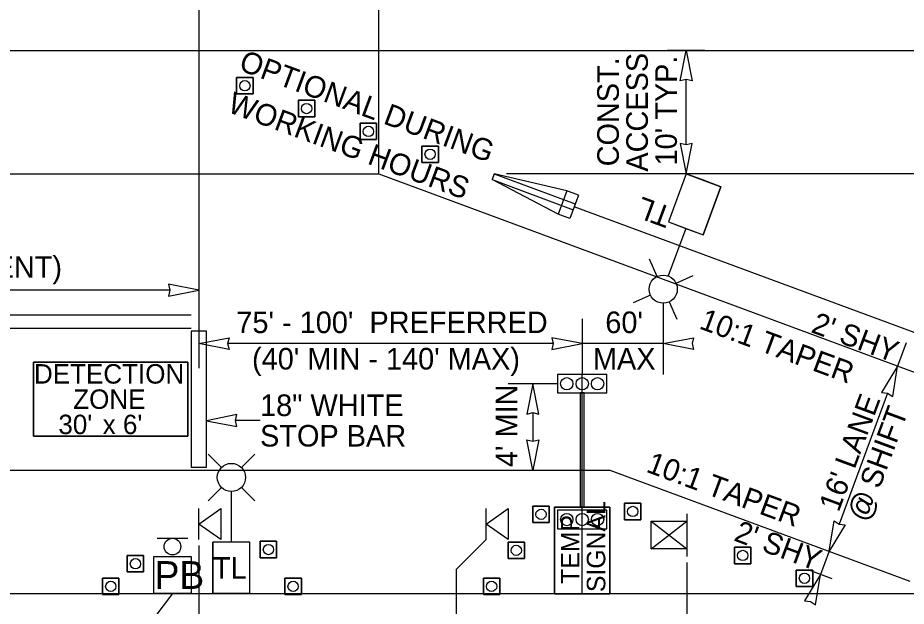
# Model space of a CAD drawing. Extents: x 99976 to 100136, y 99905 to 100011.
# Drawn here: x 100009.271 to 100012.15, y 99946.138 to 99948.045 of the extents above; entities that cross this region are included whole.
import ezdxf

# ---------------------------------------------------------------- set-up
doc = ezdxf.new("R2010")
doc.units = 0
for name, color, linetype in [('RD_ED_ShoulderPavedEdge', 7, 'Continuous'), ('RD_MK_LineEdgeWhite', 7, 'Continuous'), ('RD_MK_LineNoPass', 7, 'Continuous'), ('TR_WZ_BarrierTemp', 7, 'Continuous'), ('TR_WZ_PortableLightStandard', 7, 'Continuous'), ('TR_WZ_PortableSignMount5ftMinBlk-Wht', 7, 'Continuous'), ('TR_WZ_PortableSignMountBlk-Wht', 7, 'Continuous'), ('TR_WZ_ScaleTerminalEndSection', 7, 'Continuous'), ('TR_WZ_Sign', 7, 'Continuous'), ('TR_WZ_TempSignal', 7, 'Continuous'), ('TR_WZ_TrafficCone', 7, 'Continuous'), ('TR_WZ_WorkZoneDetails', 7, 'Continuous'), ('TR_WZ_WorkZoneTextCurrent', 7, 'Continuous')]:
    doc.layers.add(name, color=color, linetype=linetype)

msp = doc.modelspace()

# ---------------------------------------------------------------- linework, layer by layer
at = {"layer": 'RD_ED_ShoulderPavedEdge'}
for p, q in [((100000.1076, 99947.9393), (100015.45, 99947.9393)), ((100000.1076, 99946.1793), (100015.45, 99946.1793))]:
    msp.add_line(p, q, dxfattribs=at)
at = {"layer": 'RD_MK_LineEdgeWhite'}
for p, q in [((100000.1076, 99947.5393), (100010.4406, 99947.5393)), ((100010.4406, 99947.5393), (100012.9246, 99946.6193)), ((100000.1076, 99946.5793), (100011.1899, 99946.5793)), ((100011.1899, 99946.5793), (100012.1619, 99946.2193))]:
    msp.add_line(p, q, dxfattribs=at)
at = {"layer": 'RD_MK_LineNoPass'}
for p, q in [((100006.4076, 99947.0826), (100009.8326, 99947.0826)), ((100006.4076, 99947.0393), (100009.8326, 99947.0393))]:
    msp.add_line(p, q, dxfattribs=at)
at = {"layer": 'TR_WZ_BarrierTemp'}
msp.add_line((100012.9895, 99946.7232), (100011.074, 99947.4327), dxfattribs=at)
at = {"layer": 'TR_WZ_PortableLightStandard'}
for p, q in [((100011.4367, 99947.5393), (100011.3791, 99947.3837)), ((100011.4367, 99947.5393), (100011.3791, 99947.3837)), ((100011.4367, 99947.5393), (100011.5492, 99947.4976)), ((100011.5492, 99947.4976), (100011.4916, 99947.342)), ((100011.4916, 99947.342), (100011.5492, 99947.4976)), ((100011.3791, 99947.3837), (100011.4916, 99947.342)), ((100011.4353, 99947.3628), (100011.3782, 99947.2087)), ((100011.3432, 99947.2073), (100011.3178, 99947.2626)), ((100011.4039, 99947.1848), (100011.4593, 99947.2103)), ((100011.3207, 99947.1467), (100011.2655, 99947.1212)), ((100011.3815, 99947.1242), (100011.4069, 99947.0688)), ((100009.9312, 99946.5878), (100009.8881, 99946.6309)), ((100009.996, 99946.5878), (100010.0389, 99946.6309)), ((100009.9312, 99946.5231), (100009.8881, 99946.48)), ((100009.996, 99946.5231), (100010.0389, 99946.48)), ((100009.9636, 99946.3453), (100009.9636, 99946.5097)), ((100009.9036, 99946.1793), (100009.9036, 99946.3453)), ((100010.0236, 99946.3453), (100009.9036, 99946.3453)), ((100009.9036, 99946.3453), (100009.9036, 99946.1793)), ((100010.0236, 99946.1793), (100010.0236, 99946.3453)), ((100010.0236, 99946.1793), (100010.0236, 99946.3453)), ((100010.0236, 99946.1793), (100009.9036, 99946.1793))]:
    msp.add_line(p, q, dxfattribs=at)
for points in [[(100011.5492, 99947.4976), (100011.493, 99947.5185), (100011.4367, 99947.5393)], [(100011.3791, 99947.3837), (100011.4353, 99947.3628), (100011.4916, 99947.342)], [(100010.0236, 99946.3453), (100009.9636, 99946.3453), (100009.9036, 99946.3453)], [(100009.9036, 99946.1793), (100009.9636, 99946.1793), (100010.0236, 99946.1793)]]:
    msp.add_lwpolyline(points, dxfattribs=at)
for centre in [(100011.3623, 99947.1657), (100011.3623, 99947.1657), (100009.9635, 99946.5555), (100009.9635, 99946.5555)]:
    msp.add_circle(centre, 0.0457, dxfattribs=at)
at = {"layer": 'TR_WZ_PortableSignMount5ftMinBlk-Wht'}
for p, q in [((100011.4384, 99946.4376), (100011.4384, 99946.2997)), ((100011.3233, 99946.3238), (100011.4384, 99946.4134)), ((100011.3233, 99946.4134), (100011.4384, 99946.3238)), ((100011.3807, 99946.3685), (100011.3807, 99946.3685)), ((100011.3808, 99946.3686), (100011.3808, 99946.3686))]:
    msp.add_line(p, q, dxfattribs=at)
msp.add_lwpolyline([(100011.3233, 99946.3238), (100011.3233, 99946.4134), (100011.4384, 99946.4134), (100011.4384, 99946.3238)], close=True, dxfattribs=at)
at = {"layer": 'TR_WZ_PortableSignMountBlk-Wht'}
for p, q in [((100009.8576, 99946.3547), (100009.8576, 99946.4547)), ((100010.7884, 99946.3547), (100010.7884, 99946.4547))]:
    msp.add_line(p, q, dxfattribs=at)
for points in [[(100009.8576, 99946.4046), (100009.9294, 99946.4547), (100009.9294, 99946.3547)], [(100010.7884, 99946.4046), (100010.8602, 99946.4547), (100010.8602, 99946.3547)]]:
    msp.add_lwpolyline(points, close=True, dxfattribs=at)
at = {"layer": 'TR_WZ_ScaleTerminalEndSection'}
for p, q in [((100010.8149, 99947.5393), (100010.8079, 99947.5206)), ((100010.8149, 99947.5393), (100011.0775, 99947.4421)), ((100011.0504, 99947.4841), (100010.8149, 99947.5393)), ((100010.8079, 99947.5206), (100011.0705, 99947.4233)), ((100011.0226, 99947.4091), (100010.8079, 99947.5206)), ((100011.0504, 99947.4841), (100011.0226, 99947.4091)), ((100011.0879, 99947.4702), (100011.0504, 99947.4841)), ((100011.0879, 99947.4702), (100011.0601, 99947.3952)), ((100011.0601, 99947.3952), (100011.0226, 99947.4091))]:
    msp.add_line(p, q, dxfattribs=at)
at = {"layer": 'TR_WZ_Sign'}
msp.add_line((100009.7226, 99946.3583), (100009.8226, 99946.3583), dxfattribs=at)
msp.add_circle((100009.7726, 99946.3313), 0.027, dxfattribs=at)
msp.add_circle((100009.7726, 99946.3313), 0.027, dxfattribs=at)
at = {"layer": 'TR_WZ_TempSignal'}
for p, q in [((100011.02, 99946.8893), (100011.02, 99946.8293)), ((100011.1798, 99946.8893), (100011.02, 99946.8893)), ((100011.0999, 99946.1789), (100011.0999, 99946.8893)), ((100011.1798, 99946.8293), (100011.1798, 99946.8893)), ((100011.02, 99946.8293), (100011.1798, 99946.8293)), ((100011.0932, 99946.8293), (100011.0932, 99946.4591)), ((100011.1065, 99946.8293), (100011.0932, 99946.8293)), ((100011.1065, 99946.4591), (100011.1065, 99946.8293)), ((100011.0098, 99946.1789), (100011.0098, 99946.4591)), ((100011.0098, 99946.4591), (100011.1899, 99946.4591)), ((100011.0932, 99946.4591), (100011.0098, 99946.4591)), ((100011.0098, 99946.4591), (100011.0098, 99946.1789)), ((100011.0932, 99946.4591), (100011.1065, 99946.4591)), ((100011.1065, 99946.4591), (100011.0932, 99946.4591)), ((100011.1899, 99946.4591), (100011.1065, 99946.4591)), ((100011.1899, 99946.4591), (100011.1899, 99946.1789)), ((100011.1899, 99946.1789), (100011.1899, 99946.4591)), ((100011.02, 99946.4491), (100011.02, 99946.3891)), ((100011.1798, 99946.4491), (100011.02, 99946.4491)), ((100011.1798, 99946.3891), (100011.1798, 99946.4491)), ((100011.02, 99946.3891), (100011.1798, 99946.3891)), ((100011.1899, 99946.1789), (100011.0098, 99946.1789)), ((100011.0098, 99946.1789), (100011.1899, 99946.1789))]:
    msp.add_line(p, q, dxfattribs=at)
for points in [[(100011.1798, 99946.8293), (100011.1798, 99946.8893), (100011.02, 99946.8893), (100011.02, 99946.8293), (100011.1798, 99946.8293)], [(100011.1798, 99946.3891), (100011.1798, 99946.4491), (100011.02, 99946.4491), (100011.02, 99946.3891), (100011.1798, 99946.3891)]]:
    msp.add_lwpolyline(points, dxfattribs=at)
msp.add_lwpolyline([(100009.7126, 99946.2993), (100009.8326, 99946.2993), (100009.8326, 99946.1793), (100009.7126, 99946.1793)], close=True, dxfattribs=at)
msp.add_lwpolyline([(100009.7126, 99946.2993), (100009.8326, 99946.2993), (100009.8326, 99946.1793), (100009.7126, 99946.1793)], close=True, dxfattribs=at)
for centre in [(100011.0499, 99946.8593), (100011.0499, 99946.8593), (100011.0999, 99946.8593), (100011.0999, 99946.8593), (100011.1498, 99946.8593), (100011.1498, 99946.8593), (100011.0499, 99946.4191), (100011.0499, 99946.4191), (100011.0999, 99946.4191), (100011.0999, 99946.4191), (100011.1498, 99946.4191), (100011.1498, 99946.4191)]:
    msp.add_circle(centre, 0.02, dxfattribs=at)
at = {"layer": 'TR_WZ_TrafficCone'}
for points in [[(100010.0339, 99947.8518), (100009.9805, 99947.8518), (100009.9805, 99947.7984), (100010.0339, 99947.7984), (100010.0339, 99947.8518)], [(100010.0339, 99947.7984), (100009.9805, 99947.7984), (100009.9805, 99947.8518), (100010.0339, 99947.8518), (100010.0339, 99947.7984)], [(100010.2339, 99947.7777), (100010.1805, 99947.7777), (100010.1805, 99947.7244), (100010.2339, 99947.7244), (100010.2339, 99947.7777)], [(100010.2339, 99947.7244), (100010.1805, 99947.7244), (100010.1805, 99947.7777), (100010.2339, 99947.7777), (100010.2339, 99947.7244)], [(100010.4339, 99947.7036), (100010.3805, 99947.7036), (100010.3805, 99947.6503), (100010.4339, 99947.6503), (100010.4339, 99947.7036)], [(100010.4339, 99947.6503), (100010.3805, 99947.6503), (100010.3805, 99947.7036), (100010.4339, 99947.7036), (100010.4339, 99947.6503)], [(100010.6339, 99947.6295), (100010.5805, 99947.6295), (100010.5805, 99947.5762), (100010.6339, 99947.5762), (100010.6339, 99947.6295)], [(100010.6339, 99947.5762), (100010.5805, 99947.5762), (100010.5805, 99947.6295), (100010.6339, 99947.6295), (100010.6339, 99947.5762)], [(100010.9931, 99946.4626), (100010.9398, 99946.4626), (100010.9398, 99946.4093), (100010.9931, 99946.4093), (100010.9931, 99946.4626)], [(100010.9931, 99946.4093), (100010.9398, 99946.4093), (100010.9398, 99946.4626), (100010.9931, 99946.4626), (100010.9931, 99946.4093)], [(100011.237, 99946.472), (100011.2903, 99946.472), (100011.2903, 99946.4187), (100011.237, 99946.4187), (100011.237, 99946.472)], [(100011.237, 99946.4187), (100011.2903, 99946.4187), (100011.2903, 99946.472), (100011.237, 99946.472), (100011.237, 99946.4187)], [(100010.1101, 99946.3486), (100010.0568, 99946.3486), (100010.0568, 99946.2953), (100010.1101, 99946.2953), (100010.1101, 99946.3486)], [(100010.1101, 99946.2953), (100010.0568, 99946.2953), (100010.0568, 99946.3486), (100010.1101, 99946.3486), (100010.1101, 99946.2953)], [(100010.8599, 99946.346), (100010.9132, 99946.346), (100010.9132, 99946.2926), (100010.8599, 99946.2926), (100010.8599, 99946.346)], [(100010.8599, 99946.2926), (100010.9132, 99946.2926), (100010.9132, 99946.346), (100010.8599, 99946.346), (100010.8599, 99946.2926)], [(100011.5933, 99946.3294), (100011.6466, 99946.3294), (100011.6466, 99946.2761), (100011.5933, 99946.2761), (100011.5933, 99946.3294)], [(100011.5933, 99946.2761), (100011.6466, 99946.2761), (100011.6466, 99946.3294), (100011.5933, 99946.3294), (100011.5933, 99946.2761)], [(100009.6259, 99946.3026), (100009.6792, 99946.3026), (100009.6792, 99946.2493), (100009.6259, 99946.2493), (100009.6259, 99946.3026)], [(100009.6259, 99946.2493), (100009.6792, 99946.2493), (100009.6792, 99946.3026), (100009.6259, 99946.3026), (100009.6259, 99946.2493)], [(100009.5459, 99946.2293), (100009.5992, 99946.2293), (100009.5992, 99946.176), (100009.5459, 99946.176), (100009.5459, 99946.2293)], [(100009.5459, 99946.176), (100009.5992, 99946.176), (100009.5992, 99946.2293), (100009.5459, 99946.2293), (100009.5459, 99946.176)], [(100010.1901, 99946.2293), (100010.1368, 99946.2293), (100010.1368, 99946.176), (100010.1901, 99946.176), (100010.1901, 99946.2293)], [(100010.1901, 99946.176), (100010.1368, 99946.176), (100010.1368, 99946.2293), (100010.1901, 99946.2293), (100010.1901, 99946.176)], [(100010.7799, 99946.2293), (100010.8332, 99946.2293), (100010.8332, 99946.176), (100010.7799, 99946.176), (100010.7799, 99946.2293)], [(100010.7799, 99946.176), (100010.8332, 99946.176), (100010.8332, 99946.2293), (100010.7799, 99946.2293), (100010.7799, 99946.176)], [(100011.7933, 99946.2553), (100011.8466, 99946.2553), (100011.8466, 99946.202), (100011.7933, 99946.202), (100011.7933, 99946.2553)], [(100011.7933, 99946.202), (100011.8466, 99946.202), (100011.8466, 99946.2553), (100011.7933, 99946.2553), (100011.7933, 99946.202)]]:
    msp.add_lwpolyline(points, dxfattribs=at)
for centre in [(100010.0072, 99947.8251), (100010.2072, 99947.751), (100010.4072, 99947.677), (100010.6072, 99947.6029), (100011.2637, 99946.4453), (100010.9665, 99946.436), (100010.0835, 99946.3219), (100010.8865, 99946.3193), (100011.62, 99946.3027), (100009.6526, 99946.276), (100011.82, 99946.2287), (100009.5726, 99946.2026), (100010.1635, 99946.2026), (100010.8065, 99946.2026)]:
    msp.add_circle(centre, 0.0167, dxfattribs=at)
at = {"layer": 'TR_WZ_WorkZoneDetails'}
for p, q in [((100009.8576, 99948.2793), (100009.8576, 99946.9093)), ((100010.4406, 99947.5393), (100010.4406, 99948.2793)), ((100011.4967, 99947.9393), (100011.3767, 99947.9393)), ((100011.4367, 99947.633), (100011.4367, 99947.8456)), ((100012.7386, 99947.5393), (100010.8549, 99947.5393)), ((100009.7638, 99947.1626), (100006.5013, 99947.1626)), ((100011.3623, 99947.12), (100011.3623, 99946.8893)), ((100011.0999, 99947.0693), (100011.0999, 99946.8893)), ((100011.0061, 99946.9893), (100009.9513, 99946.9893)), ((100011.3623, 99946.9893), (100011.0999, 99946.9893)), ((100012.1497, 99946.9916), (100012.1219, 99946.9166)), ((100011.02, 99946.8593), (100010.86, 99946.8593)), ((100012.0894, 99946.8287), (100011.9322, 99946.4043)), ((100010.94, 99946.7656), (100010.94, 99946.673)), ((100010.0563, 99946.7401), (100009.9763, 99946.7401)), ((100010.7884, 99946.3547), (100010.6914, 99946.2577)), ((100009.8576, 99946.3347), (100009.8576, 99945.8393)), ((100011.8996, 99946.3164), (100011.8718, 99946.2414)), ((100010.6914, 99946.2577), (100010.6914, 99945.8393)), ((100011.4384, 99946.2797), (100011.4384, 99945.8393)), ((100011.9094, 99946.2275), (100011.8322, 99946.2561)), ((100009.7726, 99946.1793), (100009.7126, 99946.0993))]:
    msp.add_line(p, q, dxfattribs=at)
for points in [[(100011.4367, 99947.9393), (100011.456, 99947.841), (100011.4367, 99947.8456), (100011.4174, 99947.841)], [(100011.4367, 99947.5393), (100011.456, 99947.6376), (100011.4367, 99947.633), (100011.4174, 99947.6376)], [(100009.8576, 99947.1626), (100009.7593, 99947.1819), (100009.7638, 99947.1626), (100009.7593, 99947.1434)], [(100009.8576, 99946.9893), (100009.9558, 99947.0085), (100009.9513, 99946.9893), (100009.9558, 99946.97)], [(100011.0999, 99946.9893), (100011.0016, 99947.0085), (100011.0061, 99946.9893), (100011.0016, 99946.97)], [(100011.3623, 99946.9893), (100011.4606, 99947.0085), (100011.4561, 99946.9893), (100011.4606, 99946.97)], [(100012.1219, 99946.9166), (100012.0697, 99946.8311), (100012.0894, 99946.8287), (100012.1058, 99946.8177)], [(100010.94, 99946.8593), (100010.9207, 99946.761), (100010.94, 99946.7656), (100010.9593, 99946.761)], [(100009.8826, 99946.7393), (100009.981, 99946.7209), (100009.9763, 99946.7401), (100009.9807, 99946.7594)], [(100010.94, 99946.5793), (100010.9207, 99946.6776), (100010.94, 99946.673), (100010.9593, 99946.6776)], [(100011.8996, 99946.3164), (100011.9157, 99946.4153), (100011.9322, 99946.4043), (100011.9518, 99946.4019)], [(100011.8718, 99946.2414), (100011.8196, 99946.156), (100011.8393, 99946.1535), (100011.8558, 99946.1426)]]:
    msp.add_lwpolyline(points, close=True, dxfattribs=at)
for points in [[(100009.8326, 99946.5893), (100009.8826, 99946.5893), (100009.8826, 99947.0293), (100009.8326, 99947.0293), (100009.8326, 99946.5893)], [(100009.8326, 99946.5893), (100009.8826, 99946.5893), (100009.8826, 99947.0293), (100009.8326, 99947.0293), (100009.8326, 99946.5893)], [(100009.3226, 99946.9293), (100009.8226, 99946.9293), (100009.8226, 99946.6893), (100009.3226, 99946.6893), (100009.3226, 99946.9293)], [(100009.3226, 99946.6893), (100009.8226, 99946.6893), (100009.8226, 99946.9293), (100009.3226, 99946.9293), (100009.3226, 99946.6893)]]:
    msp.add_lwpolyline(points, dxfattribs=at)

# ---------------------------------------------------------------- texts
at = {"layer": 'TR_WZ_PortableLightStandard'}
msp.add_text('TL', height=0.07, rotation=159.6769, dxfattribs=at).set_placement((100011.3958, 99947.4287))
msp.add_text('TL', height=0.07, dxfattribs=at).set_placement((100009.9034, 99946.2273))
at = {"layer": 'TR_WZ_TempSignal'}
for s, p in [('SIGNAL', (100011.1748, 99946.184)), ('TEMP', (100011.0908, 99946.2111))]:
    msp.add_text(s, height=0.06, rotation=90, dxfattribs=at).set_placement(p)
msp.add_text('PB', height=0.09, dxfattribs=at).set_placement((100009.7148, 99946.1943))
at = {"layer": 'TR_WZ_WorkZoneDetails'}
for s, p in [('DETECTION', (100009.3239, 99946.8597)), ('ZONE', (100009.4511, 99946.7778)), ("30'", (100009.4029, 99946.6959)), ("x 6'", (100009.5465, 99946.6959))]:
    msp.add_text(s, height=0.063, dxfattribs=at).set_placement(p)
at = {"layer": 'TR_WZ_WorkZoneTextCurrent'}
for s, rotation, p in [('OPTIONAL DURING', 339.6769, (100009.984, 99947.8768)), ('ACCESS', 90, (100011.3127, 99947.5465)), ('CONST.', 90, (100011.2187, 99947.5637)), ("10' TYP.", 90, (100011.4067, 99947.5666)), ('WORKING HOURS', 339.6769, (100009.9472, 99947.7411)), ("75' - 100'  PREFERRED", 360, (100009.9795, 99947.0233)), ("60'", 360, (100011.1748, 99947.0233)), ('10:1 TAPER', 339.6769, (100011.4758, 99947.0392)), ("2' SHY", 339.6769, (100011.838, 99947.0271)), ("(40' MIN - 140' MAX)", 360, (100010.0303, 99946.9053)), ('MAX', 360, (100011.1346, 99946.9053)), ("4' MIN", 90, (100010.89, 99946.5891)), ("16' LANE", 69.6769, (100011.9308, 99946.4408)), ('SHIFT', 69.6769, (100012.063, 99946.5156)), ('10:1 TAPER', 339.6769, (100011.3038, 99946.5747)), ('@', 69.6769, (100012.023, 99946.4077)), ("2' SHY", 339.6769, (100011.5879, 99946.3519))]:
    msp.add_text(s, height=0.07, rotation=rotation, dxfattribs=at).set_placement(p)
for s, p in [('(SEE NOTE 12, WITHIN EXISTING PASSING ZONES IF PRESENT)', (100006.5333, 99947.2026)), ('18" WHITE', (100010.0563, 99946.7545)), ('STOP BAR', (100010.0563, 99946.6557))]:
    msp.add_text(s, height=0.07, dxfattribs=at).set_placement(p)

doc.saveas('drawing.dxf')
